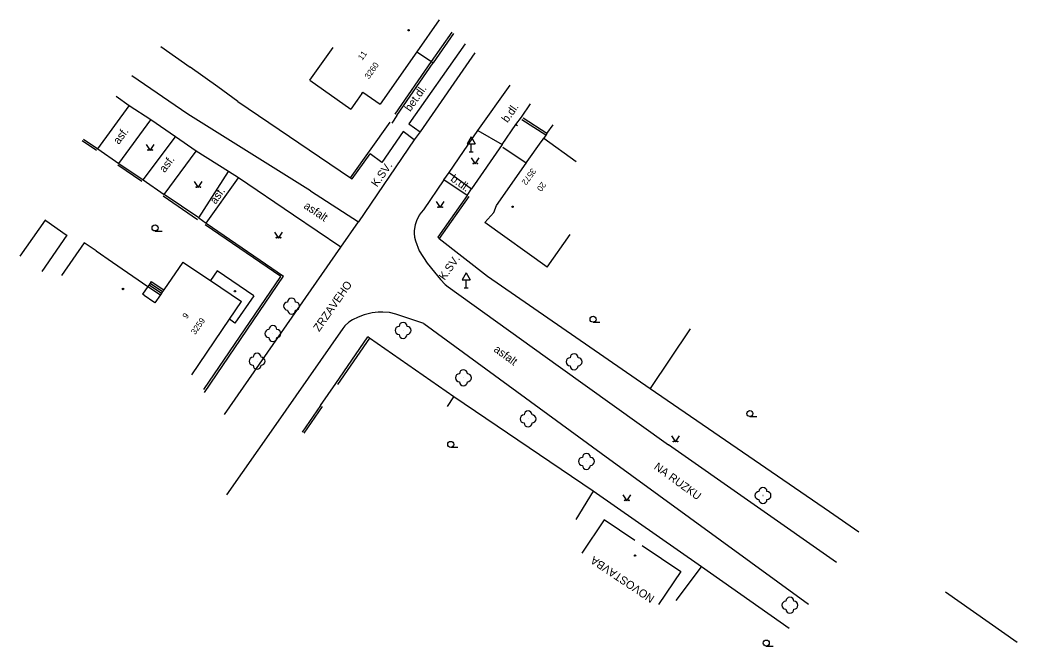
# Model space of a CAD drawing. Extents: x -668973 to -668848, y -1128129 to -1128051.
import ezdxf

# ---------------------------------------------------------------- set-up
doc = ezdxf.new("R2010")
doc.units = 0
for name, color, linetype in [('Vrstva 12', 7, 'Continuous'), ('Vrstva 13', 7, 'Continuous'), ('Vrstva 15', 7, 'Continuous'), ('Vrstva 16', 7, 'Continuous'), ('Vrstva 3', 7, 'Continuous'), ('Vrstva 50', 7, 'Continuous'), ('Vrstva 6', 7, 'Continuous'), ('Vrstva 7', 7, 'Continuous'), ('Vrstva 8', 7, 'Continuous')]:
    doc.layers.add(name, color=color, linetype=linetype)

msp = doc.modelspace()

# ---------------------------------------------------------------- linework, layer by layer
at = {"layer": 'Vrstva 12'}
for centre in [(-668938.6, -1128086.41), (-668940.93, -1128089.85), (-668924.65, -1128089.45), (-668942.91, -1128093.31), (-668903.28, -1128093.37), (-668917.12, -1128095.37), (-668909.04, -1128100.51), (-668901.74, -1128105.82), (-668879.68, -1128110.08), (-668876.32, -1128123.79)]:
    msp.add_circle(centre, 0.0005, dxfattribs=at)
for centre, start, end in [((-668938.6, -1128085.91), 0, 180), ((-668939.1, -1128086.41), 90, 270), ((-668938.1, -1128086.41), 270, 90), ((-668938.6, -1128086.91), 180, 360), ((-668940.93, -1128089.35), 0, 180), ((-668925.15, -1128089.45), 90, 270), ((-668924.65, -1128088.95), 0, 180), ((-668924.15, -1128089.45), 270, 90), ((-668941.43, -1128089.85), 90, 270), ((-668940.93, -1128090.35), 180, 360), ((-668940.43, -1128089.85), 270, 90), ((-668924.65, -1128089.95), 180, 360), ((-668943.41, -1128093.31), 90, 270), ((-668942.91, -1128092.81), 0, 180), ((-668942.41, -1128093.31), 270, 90), ((-668903.78, -1128093.37), 90, 270), ((-668903.28, -1128092.87), 0, 180), ((-668902.78, -1128093.37), 270, 90), ((-668942.91, -1128093.81), 180, 360), ((-668903.28, -1128093.87), 180, 360), ((-668917.62, -1128095.37), 90, 270), ((-668917.12, -1128094.87), 0, 180), ((-668916.62, -1128095.37), 270, 90), ((-668917.12, -1128095.87), 180, 360), ((-668909.54, -1128100.51), 90, 270), ((-668909.04, -1128100.01), 0, 180), ((-668908.54, -1128100.51), 270, 90), ((-668909.04, -1128101.01), 180, 360), ((-668902.24, -1128105.82), 90, 270), ((-668901.74, -1128105.32), 0, 180), ((-668901.24, -1128105.82), 270, 90), ((-668901.74, -1128106.32), 180, 360), ((-668879.68, -1128109.58), 0, 180), ((-668880.18, -1128110.08), 90, 270), ((-668879.18, -1128110.08), 270, 90), ((-668879.68, -1128110.58), 180, 360), ((-668876.32, -1128123.29), 0, 180), ((-668876.82, -1128123.79), 90, 270), ((-668875.82, -1128123.79), 270, 90), ((-668876.32, -1128124.29), 180, 360)]:
    msp.add_arc(centre, 0.5, start, end, dxfattribs=at)
at = {"layer": 'Vrstva 13'}
for p, q in [((-668916.9, -1128053.65), (-668923.93, -1128063.63)), ((-668915.69, -1128054.76), (-668922.54, -1128064.64)), ((-668915.31, -1128064.48), (-668911.29, -1128058.81)), ((-668958.88, -1128061.39), (-668960.53, -1128060.22)), ((-668962.82, -1128066.75), (-668958.88, -1128061.39)), ((-668956.2, -1128063.15), (-668958.88, -1128061.39)), ((-668960.18, -1128068.59), (-668956.2, -1128063.15)), ((-668953.1, -1128065.24), (-668956.2, -1128063.15)), ((-668936.23, -1128072.01), (-668951.54, -1128062.44)), ((-668906.68, -1128064.86), (-668909.66, -1128062.93)), ((-668923.93, -1128063.63), (-668922.54, -1128064.64)), ((-668910.56, -1128063.72), (-668910.35, -1128063.86)), ((-668957.16, -1128070.62), (-668953.1, -1128065.24)), ((-668950.5, -1128067.03), (-668953.1, -1128065.24)), ((-668923.26, -1128065.65), (-668930.25, -1128075.88)), ((-668924.64, -1128064.6), (-668927.3, -1128068.47)), ((-668923.26, -1128065.65), (-668924.64, -1128064.6)), ((-668922.54, -1128064.64), (-668923.26, -1128065.65)), ((-668918.88, -1128069.73), (-668915.31, -1128064.48)), ((-668915.31, -1128064.48), (-668912.26, -1128066.22)), ((-668954.52, -1128072.45), (-668950.5, -1128067.03)), ((-668946.46, -1128069.61), (-668950.5, -1128067.03)), ((-668927.3, -1128068.47), (-668928.79, -1128067.4)), ((-668950.2, -1128075.4), (-668946.46, -1128069.61)), ((-668949.26, -1128076.04), (-668945.24, -1128070.37)), ((-668945.24, -1128070.37), (-668946.46, -1128069.61)), ((-668938.34, -1128075.05), (-668945.24, -1128070.37)), ((-668919.57, -1128070.62), (-668918.88, -1128069.73)), ((-668916.67, -1128072.58), (-668919.57, -1128070.62)), ((-668918.88, -1128069.73), (-668916.09, -1128071.75)), ((-668936.23, -1128072.01), (-668930.25, -1128075.88)), ((-668932.43, -1128079.03), (-668938.34, -1128075.05)), ((-668932.43, -1128079.03), (-668930.25, -1128075.88)), ((-668946.99, -1128099.95), (-668932.43, -1128079.03)), ((-668922.06, -1128088.57), (-668899.92, -1128104.8)), ((-668870.48, -1128118.47), (-668891.51, -1128103.74)), ((-668899.92, -1128104.8), (-668873.98, -1128123.65))]:
    msp.add_line(p, q, dxfattribs=at)
for points in [[(-668951.54, -1128062.44), (-668958.54, -1128057.62)], [(-668919.57, -1128070.62), (-668922.12, -1128074.36), (-668922.4, -1128074.71), (-668922.63, -1128075.03), (-668922.99, -1128075.74), (-668923.16, -1128076.26), (-668923.28, -1128076.96), (-668923.28, -1128077.35), (-668923.23, -1128077.78), (-668923.09, -1128078.24), (-668922.66, -1128079.52), (-668921.66, -1128081.05), (-668920.73, -1128082.17), (-668919.98, -1128083.09), (-668919.4, -1128083.71), (-668919.02, -1128084.02), (-668905.26, -1128093.88), (-668891.51, -1128103.74)], [(-668922.06, -1128088.57), (-668923.81, -1128087.99), (-668925.56, -1128087.41), (-668926.37, -1128087.22), (-668927.21, -1128087.15), (-668927.78, -1128087.17), (-668928.54, -1128087.27), (-668929.53, -1128087.51), (-668930.28, -1128087.79), (-668930.99, -1128088.14), (-668931.43, -1128088.43), (-668931.94, -1128088.89), (-668932.18, -1128089.2), (-668940.87, -1128101.62), (-668946.71, -1128109.98)]]:
    msp.add_lwpolyline(points, dxfattribs=at)
at = {"layer": 'Vrstva 3'}
for p, q in [((-668955.65, -1128077.03), (-668954.78, -1128077.03)), ((-668900.92, -1128088.43), (-668900.05, -1128088.43)), ((-668881.32, -1128100.22), (-668880.45, -1128100.22)), ((-668918.7, -1128104.06), (-668917.83, -1128104.06)), ((-668879.27, -1128128.9), (-668878.4, -1128128.9))]:
    msp.add_line(p, q, dxfattribs=at)
for points in [[(-668956.77, -1128066.2), (-668956.27, -1128066.95), (-668955.77, -1128066.2)], [(-668916.13, -1128067.89), (-668915.63, -1128068.64), (-668915.13, -1128067.89)], [(-668950.75, -1128070.86), (-668950.25, -1128071.61), (-668949.75, -1128070.86)], [(-668920.53, -1128073.35), (-668920.03, -1128074.1), (-668919.53, -1128073.35)], [(-668940.74, -1128077.16), (-668940.24, -1128077.91), (-668939.74, -1128077.16)], [(-668891.12, -1128102.63), (-668890.62, -1128103.38), (-668890.12, -1128102.63)], [(-668897.21, -1128109.99), (-668896.71, -1128110.74), (-668896.21, -1128109.99)]]:
    msp.add_lwpolyline(points, dxfattribs=at)
for centre, radius in [((-668956.52, -1128066.9), 0.05), ((-668956.02, -1128066.9), 0.05), ((-668915.88, -1128068.59), 0.05), ((-668915.38, -1128068.59), 0.05), ((-668950.5, -1128071.56), 0.05), ((-668950, -1128071.56), 0.05), ((-668920.28, -1128074.05), 0.05), ((-668919.78, -1128074.05), 0.05), ((-668955.65, -1128076.65), 0.375), ((-668940.49, -1128077.86), 0.05), ((-668939.99, -1128077.86), 0.05), ((-668900.92, -1128088.05), 0.375), ((-668881.32, -1128099.84), 0.375), ((-668918.7, -1128103.69), 0.375), ((-668890.87, -1128103.33), 0.05), ((-668890.37, -1128103.33), 0.05), ((-668896.96, -1128110.69), 0.05), ((-668896.46, -1128110.69), 0.05), ((-668879.27, -1128128.52), 0.375)]:
    msp.add_circle(centre, radius, dxfattribs=at)
at = {"layer": 'Vrstva 50'}
for p, q in [((-668929.81, -1128059.83), (-668930.38, -1128060.66)), ((-668906.68, -1128064.86), (-668905.9, -1128063.77)), ((-668909.14, -1128068.36), (-668907.4, -1128065.88)), ((-668913.31, -1128074.72), (-668912.99, -1128073.83)), ((-668969.3, -1128075.73), (-668966.77, -1128077.49)), ((-668963.02, -1128079.51), (-668960.97, -1128080.93)), ((-668957.01, -1128085.06), (-668955.82, -1128085.89))]:
    msp.add_line(p, q, dxfattribs=at)
at = {"layer": 'Vrstva 6'}
for p, q in [((-668920.16, -1128050.65), (-668922.92, -1128054.62)), ((-668936.3, -1128058.19), (-668933.41, -1128054.11)), ((-668922.92, -1128054.62), (-668927.52, -1128061.17)), ((-668936.3, -1128058.19), (-668931.18, -1128061.82)), ((-668930.38, -1128060.66), (-668931.18, -1128061.82)), ((-668929.81, -1128059.83), (-668929.69, -1128059.67)), ((-668929.69, -1128059.67), (-668927.52, -1128061.17)), ((-668907.25, -1128065.68), (-668907.08, -1128065.44)), ((-668906.82, -1128065.07), (-668907.08, -1128065.44)), ((-668907.08, -1128065.44), (-668903.01, -1128068.34)), ((-668906.68, -1128064.86), (-668906.82, -1128065.07)), ((-668907.4, -1128065.88), (-668907.25, -1128065.68)), ((-668912.99, -1128073.83), (-668909.28, -1128068.56)), ((-668909.28, -1128068.56), (-668909.14, -1128068.36)), ((-668914.46, -1128075.95), (-668913.31, -1128074.72)), ((-668969.4, -1128075.66), (-668972.54, -1128080.18)), ((-668969.3, -1128075.73), (-668969.4, -1128075.66)), ((-668906.67, -1128081.54), (-668914.46, -1128075.95)), ((-668966.67, -1128077.56), (-668969.8, -1128082.08)), ((-668966.77, -1128077.49), (-668966.67, -1128077.56)), ((-668906.67, -1128081.54), (-668903.76, -1128077.48)), ((-668964.51, -1128078.49), (-668967.34, -1128082.6)), ((-668963.02, -1128079.51), (-668964.51, -1128078.49)), ((-668960.97, -1128080.93), (-668956.56, -1128083.97)), ((-668952.19, -1128080.91), (-668954.57, -1128084.39)), ((-668952.19, -1128080.91), (-668948.74, -1128083.22)), ((-668947.89, -1128082), (-668948.74, -1128083.22)), ((-668943.29, -1128085.14), (-668947.89, -1128082)), ((-668956.56, -1128083.97), (-668957.22, -1128084.92)), ((-668948.74, -1128083.22), (-668944.84, -1128085.82)), ((-668957.01, -1128085.06), (-668957.22, -1128084.92)), ((-668954.98, -1128084.99), (-668955.67, -1128085.99)), ((-668954.86, -1128084.8), (-668954.98, -1128084.99)), ((-668954.71, -1128084.6), (-668954.86, -1128084.8)), ((-668954.57, -1128084.39), (-668954.71, -1128084.6)), ((-668943.29, -1128085.14), (-668945.68, -1128088.54)), ((-668955.82, -1128085.89), (-668955.67, -1128085.99)), ((-668946.36, -1128088.06), (-668944.84, -1128085.82)), ((-668951.05, -1128094.98), (-668946.36, -1128088.06)), ((-668945.68, -1128088.54), (-668946.36, -1128088.06)), ((-668899.54, -1128113.14), (-668902.32, -1128117.3)), ((-668895.69, -1128115.72), (-668899.54, -1128113.14)), ((-668894.78, -1128116.33), (-668889.94, -1128119.57)), ((-668889.94, -1128119.57), (-668892.72, -1128123.72))]:
    msp.add_line(p, q, dxfattribs=at)
at = {"layer": 'Vrstva 7'}
for centre in [(-668923.98, -1128051.94), (-668910.97, -1128074), (-668959.66, -1128084.27), (-668945.68, -1128084.56), (-668895.66, -1128117.58)]:
    msp.add_circle(centre, 0.0875, dxfattribs=at)
at = {"layer": 'Vrstva 8'}
for p, q in [((-668921.09, -1128055.86), (-668918.52, -1128052.16)), ((-668918.34, -1128052.33), (-668920.88, -1128056)), ((-668954.92, -1128053.97), (-668951.28, -1128056.56)), ((-668922.92, -1128054.62), (-668921.09, -1128055.86)), ((-668947.82, -1128059.01), (-668951.28, -1128056.56)), ((-668925.65, -1128062.44), (-668921.09, -1128055.86)), ((-668925.44, -1128062.58), (-668920.88, -1128056)), ((-668921.09, -1128055.86), (-668920.88, -1128056)), ((-668945.32, -1128060.83), (-668947.82, -1128059.01)), ((-668945.32, -1128060.83), (-668931.22, -1128070.38)), ((-668909.87, -1128062.79), (-668908.74, -1128061.15)), ((-668925.44, -1128062.58), (-668926.08, -1128063.57)), ((-668910.56, -1128063.72), (-668909.87, -1128062.79)), ((-668906.82, -1128065.07), (-668909.82, -1128063.14)), ((-668931.22, -1128070.38), (-668926.28, -1128063.43)), ((-668912.26, -1128066.22), (-668910.56, -1128063.72)), ((-668916.16, -1128065.26), (-668916.66, -1128066.13)), ((-668916.16, -1128065.26), (-668915.66, -1128066.13)), ((-668962.96, -1128066.96), (-668964.76, -1128065.75)), ((-668962.82, -1128066.75), (-668960.18, -1128068.59)), ((-668916.66, -1128066.13), (-668915.66, -1128066.13)), ((-668916.16, -1128067.13), (-668916.16, -1128066.13)), ((-668912.26, -1128066.22), (-668916.09, -1128071.75)), ((-668909.28, -1128068.56), (-668912.2, -1128066.57)), ((-668931.01, -1128070.52), (-668928.79, -1128067.4)), ((-668916.41, -1128067.13), (-668915.91, -1128067.13)), ((-668957.3, -1128070.83), (-668960.32, -1128068.8)), ((-668960.18, -1128068.59), (-668957.16, -1128070.62)), ((-668957.16, -1128070.62), (-668954.52, -1128072.45)), ((-668931.22, -1128070.38), (-668931.01, -1128070.52)), ((-668916.67, -1128072.58), (-668916.09, -1128071.75)), ((-668950.34, -1128075.61), (-668954.66, -1128072.66)), ((-668950.2, -1128075.4), (-668954.52, -1128072.45)), ((-668916.67, -1128072.58), (-668920.33, -1128077.8)), ((-668916.46, -1128072.72), (-668920.13, -1128077.96)), ((-668950.2, -1128075.4), (-668949.26, -1128076.04)), ((-668939.94, -1128082.71), (-668949.4, -1128076.24)), ((-668949.26, -1128076.04), (-668939.6, -1128082.65)), ((-668920.33, -1128077.8), (-668920.13, -1128077.96)), ((-668920.13, -1128077.96), (-668914.09, -1128082.66)), ((-668949.55, -1128096.83), (-668939.94, -1128082.71)), ((-668949.49, -1128097.19), (-668939.6, -1128082.65)), ((-668916.77, -1128082.24), (-668917.27, -1128083.11)), ((-668917.27, -1128083.11), (-668916.27, -1128083.11)), ((-668916.77, -1128082.24), (-668916.27, -1128083.11)), ((-668916.77, -1128084.11), (-668916.77, -1128083.11)), ((-668914.09, -1128082.66), (-668893.8, -1128096.7)), ((-668956.4, -1128083.74), (-668956.56, -1128083.97)), ((-668956.56, -1128083.97), (-668954.98, -1128084.99)), ((-668956.26, -1128083.54), (-668956.4, -1128083.74)), ((-668956.4, -1128083.74), (-668954.86, -1128084.8)), ((-668956.12, -1128083.33), (-668956.26, -1128083.54)), ((-668956.26, -1128083.54), (-668954.71, -1128084.6)), ((-668956.12, -1128083.33), (-668954.57, -1128084.39)), ((-668917.02, -1128084.11), (-668916.52, -1128084.11)), ((-668888.77, -1128089.26), (-668893.8, -1128096.7)), ((-668933.06, -1128096.07), (-668929.07, -1128090.26)), ((-668928.86, -1128090.4), (-668932.85, -1128096.21)), ((-668928.86, -1128090.4), (-668929.07, -1128090.26)), ((-668918.33, -1128097.74), (-668928.86, -1128090.4)), ((-668934.97, -1128098.82), (-668933.06, -1128096.07)), ((-668893.8, -1128096.7), (-668871.37, -1128112.1)), ((-668919.1, -1128098.95), (-668918.33, -1128097.74)), ((-668900.92, -1128109.53), (-668918.33, -1128097.74)), ((-668934.97, -1128098.82), (-668937.27, -1128102.17)), ((-668934.76, -1128098.96), (-668937.06, -1128102.31)), ((-668900.92, -1128109.53), (-668903.08, -1128113.09)), ((-668887.37, -1128118.98), (-668900.92, -1128109.53)), ((-668871.37, -1128112.1), (-668867.72, -1128114.62)), ((-668890.54, -1128123.22), (-668887.37, -1128118.98)), ((-668876.4, -1128126.72), (-668887.37, -1128118.98)), ((-668856.87, -1128122.13), (-668847.93, -1128128.41))]:
    msp.add_line(p, q, dxfattribs=at)
msp.add_lwpolyline([(-668964.61, -1128065.55), (-668962.82, -1128066.75)], dxfattribs=at)

# ---------------------------------------------------------------- texts
at = {"layer": 'Vrstva 15'}
for s, rotation, p in [('ZRZAVEHO', 55.043, (-668935.15, -1128089.68)), ('NA RUZKU', 323.9892, (-668893.39, -1128106.69))]:
    msp.add_text(s, height=1, rotation=rotation, dxfattribs=at).set_placement(p)
at = {"layer": 'Vrstva 16'}
for s, rotation, p in [('bet.dl.', 54.8137, (-668923.76, -1128062.18)), ('b.dl.', 54.5334, (-668911.62, -1128063.56)), ('asf.', 53.4257, (-668960.19, -1128066.28)), ('asf.', 53.4257, (-668954.44, -1128069.8)), ('K.SV.', 54.6538, (-668927.92, -1128071.6)), ('b.dl.', 324.5334, (-668918.81, -1128070.7)), ('asf.', 54.6282, (-668948.09, -1128073.75)), ('asfalt', 326.04, (-668937.15, -1128074.1)), ('K.SV.', 54.686, (-668919.46, -1128083.26)), ('asfalt', 323.7566, (-668913.41, -1128092)), ('NOVOSTAVBA', 146.2054, (-668893.15, -1128122.73))]:
    msp.add_text(s, height=1, rotation=rotation, dxfattribs=at).set_placement(p)
at = {"layer": 'Vrstva 6'}
for s, rotation, p in [('11', 54.9371, (-668929.76, -1128055.76)), ('3260', 54.9371, (-668928.92, -1128058.1)), ('3572', 234.5334, (-668908.59, -1128069.12)), ('20', 234.5334, (-668907.34, -1128070.82)), ('9', 54.8525, (-668951.68, -1128088.07)), ('3259', 54.8525, (-668950.63, -1128090.04))]:
    msp.add_text(s, height=0.75, rotation=rotation, dxfattribs=at).set_placement(p)

doc.saveas('drawing.dxf')
